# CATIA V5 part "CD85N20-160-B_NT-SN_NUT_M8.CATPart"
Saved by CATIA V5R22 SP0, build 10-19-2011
Part number: CD85N20-160-B_NT-SN_NUT_M8
Revision: ANY
Definition: UNKNOWN
Nomenclature: CD85N20-160-B_NT-SN_NUT_M8
Source: Unknown
Bounding box of the stored display mesh (mm): x -6.5 to 6.5, y -7.506 to 7.506, z -1.181 to 3.819
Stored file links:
  D:\PER\CAO_PER_MODIF_2025\CAO_PER_pick&place_2024P\Sous_Ensemble_Boite\Verin\CD85N20-160-B_NT-SN_NUT_M8.CATPart
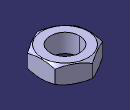
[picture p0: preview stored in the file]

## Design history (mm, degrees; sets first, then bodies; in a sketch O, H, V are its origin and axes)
Body1 "REVOLVE" (main body)
  Solid1: solid without history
